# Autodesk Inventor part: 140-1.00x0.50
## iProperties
Created: 2007-06
Part Number: 140-1.00x0.50
Document SubType Name: Modeling
Designer: btaylor
Density: 1 g/cm^3
Author: btaylor
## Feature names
1. Extrusion1
2. Extrusion2
3. Extrusion3
4. Extrusion4
5. Fillet1
6. Fillet2
7. Chamfer1
8. Chamfer2
